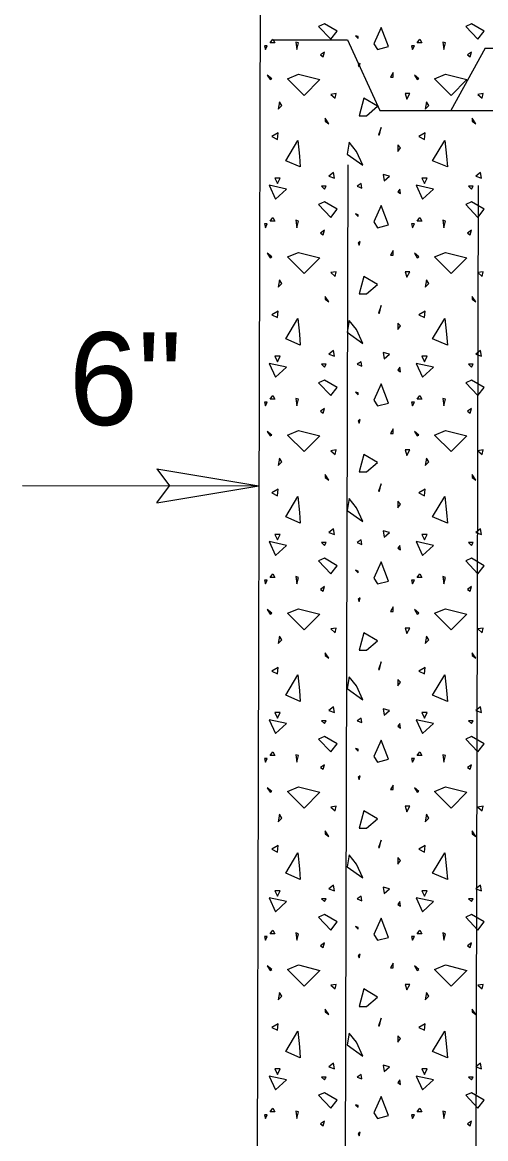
# Model space of a CAD drawing. Extents: x 9.6 to 16.8, y 2.2 to 12.2.
# Drawn here: x 14.697 to 14.996, y 7.48 to 8.202 of the extents above; entities that cross this region are included whole.
import ezdxf

# ---------------------------------------------------------------- set-up
doc = ezdxf.new("R2010")
doc.units = 0
for name, color, linetype in [('DETL-DIMS', 7, 'Continuous'), ('DETL-LINE', 7, 'Continuous'), ('DETL-NOTE', 7, 'Continuous'), ('DETL-PATT', 7, 'Continuous')]:
    doc.layers.add(name, color=color, linetype=linetype)

msp = doc.modelspace()

# ---------------------------------------------------------------- linework, layer by layer
at = {"layer": 'DETL-DIMS'}
for p, q in [((14.78357, 7.91357), (14.84941, 7.90247)), ((14.78357, 7.91357), (14.79176, 7.90259)), ((14.69659, 7.90278), (14.84941, 7.90247)), ((14.78349, 7.89161), (14.79176, 7.90259)), ((14.78349, 7.89161), (14.84941, 7.90247))]:
    msp.add_line(p, q, dxfattribs=at)
at = {"layer": 'DETL-LINE'}
for p, q in [((14.85165, 8.75561), (14.84702, 6.99)), ((14.85804, 8.19102), (14.90675, 8.1909)), ((14.90675, 8.1909), (14.92769, 8.14525)), ((14.99573, 8.18549), (14.97361, 8.14518)), ((14.99573, 8.18549), (16.02733, 8.18278)), ((14.92769, 8.14525), (14.97361, 8.14518)), ((14.97361, 8.14518), (16.04459, 8.14518)), ((14.90698, 8.11008), (14.90412, 7.02231)), ((14.99129, 8.09671), (14.98867, 7.08824))]:
    msp.add_line(p, q, dxfattribs=at)
at = {"layer": 'DETL-PATT'}
for points in [[(14.88812, 8.19961), (14.89588, 8.19129), (14.90012, 8.19651), (14.8918, 8.20133)], [(14.98314, 8.19961), (14.9909, 8.19129), (14.99514, 8.19651), (14.98682, 8.20133)], [(14.91369, 8.19298), (14.912, 8.19357), (14.91369, 8.19184)], [(14.92624, 8.18467), (14.93329, 8.18651), (14.92851, 8.1989), (14.92384, 8.18831)], [(14.8531, 8.18706), (14.85369, 8.18467), (14.85494, 8.18706)], [(14.85847, 8.19129), (14.85976, 8.1889), (14.85678, 8.1889)], [(14.87329, 8.18945), (14.874, 8.18467), (14.87514, 8.1889)], [(14.94812, 8.18706), (14.94871, 8.18467), (14.94996, 8.18706)], [(14.95349, 8.19129), (14.95475, 8.1889), (14.9518, 8.1889)], [(14.96831, 8.18945), (14.96902, 8.18467), (14.97016, 8.1889)], [(14.88941, 8.18114), (14.8911, 8.18), (14.8918, 8.18298)], [(14.98439, 8.18114), (14.98612, 8.18), (14.98682, 8.18298)], [(14.91494, 8.17576), (14.91369, 8.17463), (14.91439, 8.17337)], [(14.85678, 8.16518), (14.85792, 8.16573), (14.85494, 8.16816)], [(14.87514, 8.16871), (14.88882, 8.16518), (14.87867, 8.15502), (14.86792, 8.16573)], [(14.93627, 8.16984), (14.93459, 8.16686), (14.93627, 8.16686)], [(14.9518, 8.16518), (14.95294, 8.16573), (14.94996, 8.16816)], [(14.97016, 8.16871), (14.98384, 8.16518), (14.97369, 8.15502), (14.96294, 8.16573)], [(14.86271, 8.1509), (14.862, 8.14612), (14.86439, 8.14851)], [(14.89588, 8.15557), (14.89886, 8.15318), (14.89941, 8.15616)], [(14.91906, 8.14188), (14.92624, 8.14796), (14.91733, 8.15318), (14.91439, 8.14188)], [(14.94404, 8.15616), (14.94518, 8.15263), (14.94698, 8.15616)], [(14.95773, 8.1509), (14.95702, 8.14612), (14.95941, 8.14851)], [(14.9909, 8.15557), (14.99388, 8.15318), (14.99443, 8.15616)], [(14.89235, 8.1402), (14.89235, 8.13835), (14.89475, 8.13667)], [(14.98737, 8.1402), (14.98737, 8.13835), (14.98976, 8.13667)], [(14.85792, 8.12831), (14.86145, 8.12651), (14.862, 8.13075)], [(14.92682, 8.12945), (14.92737, 8.12945), (14.92851, 8.13427)], [(14.95294, 8.12831), (14.95647, 8.12651), (14.95702, 8.13075)], [(14.87569, 8.11576), (14.87627, 8.10871), (14.86682, 8.11278), (14.87459, 8.12592)], [(14.90776, 8.12467), (14.90663, 8.11702), (14.91663, 8.10984), (14.91255, 8.11875)], [(14.93922, 8.12298), (14.93922, 8.11875), (14.94106, 8.12114)], [(14.97071, 8.11576), (14.97129, 8.10871), (14.9618, 8.11278), (14.96957, 8.12592)], [(14.85976, 8.10149), (14.86145, 8.09796), (14.86329, 8.10149)], [(14.89773, 8.10518), (14.89475, 8.10278), (14.89827, 8.10149)], [(14.92976, 8.10392), (14.93035, 8.0998), (14.93388, 8.10278)], [(14.95475, 8.10149), (14.95647, 8.09796), (14.95827, 8.10149)], [(14.99275, 8.10518), (14.98976, 8.10278), (14.99329, 8.10149)], [(14.85608, 8.09686), (14.86031, 8.08796), (14.86737, 8.09443)], [(14.88996, 8.09627), (14.8918, 8.09443), (14.89294, 8.09627)], [(14.9131, 8.09627), (14.91608, 8.09502), (14.91553, 8.09796)], [(14.93922, 8.09263), (14.94106, 8.09149), (14.94051, 8.09443)], [(14.9511, 8.09686), (14.95533, 8.08796), (14.96239, 8.09443)], [(14.98498, 8.09627), (14.98682, 8.09443), (14.98792, 8.09627)], [(14.88812, 8.08443), (14.89588, 8.07608), (14.90012, 8.08133), (14.8918, 8.08612)], [(14.98314, 8.08443), (14.9909, 8.07608), (14.99514, 8.08133), (14.98682, 8.08612)], [(14.91369, 8.0778), (14.912, 8.07835), (14.91369, 8.07667)], [(14.92624, 8.06945), (14.93329, 8.07129), (14.92851, 8.08373), (14.92384, 8.07314)], [(14.8531, 8.07184), (14.85369, 8.06945), (14.85494, 8.07184)], [(14.85847, 8.07608), (14.85976, 8.07369), (14.85678, 8.07369)], [(14.87329, 8.07427), (14.874, 8.06945), (14.87514, 8.07369)], [(14.94812, 8.07184), (14.94871, 8.06945), (14.94996, 8.07184)], [(14.95349, 8.07608), (14.95475, 8.07369), (14.9518, 8.07369)], [(14.96831, 8.07427), (14.96902, 8.06945), (14.97016, 8.07369)], [(14.88941, 8.06592), (14.8911, 8.06478), (14.8918, 8.06776)], [(14.98439, 8.06592), (14.98612, 8.06478), (14.98682, 8.06776)], [(14.91494, 8.06055), (14.91369, 8.05945), (14.91439, 8.05816)], [(14.85678, 8.04996), (14.85792, 8.05055), (14.85494, 8.05294)], [(14.87514, 8.05349), (14.88882, 8.04996), (14.87867, 8.0398), (14.86792, 8.05055)], [(14.93627, 8.05463), (14.93459, 8.05169), (14.93627, 8.05169)], [(14.9518, 8.04996), (14.95294, 8.05055), (14.94996, 8.05294)], [(14.97016, 8.05349), (14.98384, 8.04996), (14.97369, 8.0398), (14.96294, 8.05055)], [(14.86271, 8.03573), (14.862, 8.0309), (14.86439, 8.03333)], [(14.89588, 8.04039), (14.89886, 8.03796), (14.89941, 8.04094)], [(14.91906, 8.02667), (14.92624, 8.03275), (14.91733, 8.03796), (14.91439, 8.02667)], [(14.94404, 8.04094), (14.94518, 8.03741), (14.94698, 8.04094)], [(14.95773, 8.03573), (14.95702, 8.0309), (14.95941, 8.03333)], [(14.9909, 8.04039), (14.99388, 8.03796), (14.99443, 8.04094)], [(14.89235, 8.02498), (14.89235, 8.02314), (14.89475, 8.02145)], [(14.98737, 8.02498), (14.98737, 8.02314), (14.98976, 8.02145)], [(14.85792, 8.01314), (14.86145, 8.01129), (14.862, 8.01553)], [(14.92682, 8.01427), (14.92737, 8.01427), (14.92851, 8.01906)], [(14.95294, 8.01314), (14.95647, 8.01129), (14.95702, 8.01553)], [(14.87569, 8.00055), (14.87627, 7.99349), (14.86682, 7.99761), (14.87459, 8.01075)], [(14.90776, 8.00945), (14.90663, 8.00184), (14.91663, 7.99463), (14.91255, 8.00353)], [(14.93922, 8.00776), (14.93922, 8.00353), (14.94106, 8.00592)], [(14.97071, 8.00055), (14.97129, 7.99349), (14.9618, 7.99761), (14.96957, 8.01075)], [(14.85976, 7.98631), (14.86145, 7.98278), (14.86329, 7.98631)], [(14.89773, 7.98996), (14.89475, 7.98757), (14.89827, 7.98631)], [(14.92976, 7.98871), (14.93035, 7.98463), (14.93388, 7.98757)], [(14.95475, 7.98631), (14.95647, 7.98278), (14.95827, 7.98631)], [(14.99275, 7.98996), (14.98976, 7.98757), (14.99329, 7.98631)], [(14.85608, 7.98165), (14.86031, 7.97275), (14.86737, 7.97925)], [(14.88996, 7.9811), (14.8918, 7.97925), (14.89294, 7.9811)], [(14.9131, 7.9811), (14.91608, 7.9798), (14.91553, 7.98278)], [(14.93922, 7.97741), (14.94106, 7.97627), (14.94051, 7.97925)], [(14.9511, 7.98165), (14.95533, 7.97275), (14.96239, 7.97925)], [(14.98498, 7.9811), (14.98682, 7.97925), (14.98792, 7.9811)], [(14.88812, 7.96922), (14.89588, 7.9609), (14.90012, 7.96612), (14.8918, 7.9709)], [(14.98314, 7.96922), (14.9909, 7.9609), (14.99514, 7.96612), (14.98682, 7.9709)], [(14.91369, 7.96259), (14.912, 7.96314), (14.91369, 7.96145)], [(14.92624, 7.95427), (14.93329, 7.95608), (14.92851, 7.96851), (14.92384, 7.95792)], [(14.8531, 7.95667), (14.85369, 7.95427), (14.85494, 7.95667)], [(14.85847, 7.9609), (14.85976, 7.95851), (14.85678, 7.95851)], [(14.87329, 7.95906), (14.874, 7.95427), (14.87514, 7.95851)], [(14.94812, 7.95667), (14.94871, 7.95427), (14.94996, 7.95667)], [(14.95349, 7.9609), (14.95475, 7.95851), (14.9518, 7.95851)], [(14.96831, 7.95906), (14.96902, 7.95427), (14.97016, 7.95851)], [(14.88941, 7.95075), (14.8911, 7.94961), (14.8918, 7.95255)], [(14.98439, 7.95075), (14.98612, 7.94961), (14.98682, 7.95255)], [(14.91494, 7.94537), (14.91369, 7.94424), (14.91439, 7.94298)], [(14.85678, 7.93478), (14.85792, 7.93533), (14.85494, 7.93773)], [(14.87514, 7.93831), (14.88882, 7.93478), (14.87867, 7.92463), (14.86792, 7.93533)], [(14.93627, 7.93945), (14.93459, 7.93647), (14.93627, 7.93647)], [(14.9518, 7.93478), (14.95294, 7.93533), (14.94996, 7.93773)], [(14.97016, 7.93831), (14.98384, 7.93478), (14.97369, 7.92463), (14.96294, 7.93533)], [(14.86271, 7.92051), (14.862, 7.91573), (14.86439, 7.91812)], [(14.89588, 7.92518), (14.89886, 7.92278), (14.89941, 7.92573)], [(14.91906, 7.91149), (14.92624, 7.91757), (14.91733, 7.92278), (14.91439, 7.91149)], [(14.94404, 7.92573), (14.94518, 7.9222), (14.94698, 7.92573)], [(14.95773, 7.92051), (14.95702, 7.91573), (14.95941, 7.91812)], [(14.9909, 7.92518), (14.99388, 7.92278), (14.99443, 7.92573)], [(14.89235, 7.9098), (14.89235, 7.90796), (14.89475, 7.90627)], [(14.98737, 7.9098), (14.98737, 7.90796), (14.98976, 7.90627)], [(14.85792, 7.89792), (14.86145, 7.89608), (14.862, 7.90031)], [(14.92682, 7.89906), (14.92737, 7.89906), (14.92851, 7.90384)], [(14.95294, 7.89792), (14.95647, 7.89608), (14.95702, 7.90031)], [(14.87569, 7.88537), (14.87627, 7.87831), (14.86682, 7.88239), (14.87459, 7.89553)], [(14.90776, 7.89427), (14.90663, 7.88663), (14.91663, 7.87945), (14.91255, 7.88831)], [(14.93922, 7.89255), (14.93922, 7.88831), (14.94106, 7.89075)], [(14.97071, 7.88537), (14.97129, 7.87831), (14.9618, 7.88239), (14.96957, 7.89553)], [(14.85976, 7.8711), (14.86145, 7.86757), (14.86329, 7.8711)], [(14.89773, 7.87478), (14.89475, 7.87239), (14.89827, 7.8711)], [(14.92976, 7.87349), (14.93035, 7.86941), (14.93388, 7.87239)], [(14.95475, 7.8711), (14.95647, 7.86757), (14.95827, 7.8711)], [(14.99275, 7.87478), (14.98976, 7.87239), (14.99329, 7.8711)], [(14.85608, 7.86643), (14.86031, 7.85757), (14.86737, 7.86404)], [(14.88996, 7.86588), (14.8918, 7.86404), (14.89294, 7.86588)], [(14.9131, 7.86588), (14.91608, 7.86463), (14.91553, 7.86757)], [(14.93922, 7.8622), (14.94106, 7.8611), (14.94051, 7.86404)], [(14.9511, 7.86643), (14.95533, 7.85757), (14.96239, 7.86404)], [(14.98498, 7.86588), (14.98682, 7.86404), (14.98792, 7.86588)], [(14.88812, 7.85404), (14.89588, 7.84569), (14.90012, 7.8509), (14.8918, 7.85573)], [(14.98314, 7.85404), (14.9909, 7.84569), (14.99514, 7.8509), (14.98682, 7.85573)], [(14.91369, 7.84737), (14.912, 7.84796), (14.91369, 7.84627)], [(14.92624, 7.83906), (14.93329, 7.8409), (14.92851, 7.85333), (14.92384, 7.84275)], [(14.8531, 7.84145), (14.85369, 7.83906), (14.85494, 7.84145)], [(14.85847, 7.84569), (14.85976, 7.84329), (14.85678, 7.84329)], [(14.87329, 7.84384), (14.874, 7.83906), (14.87514, 7.84329)], [(14.94812, 7.84145), (14.94871, 7.83906), (14.94996, 7.84145)], [(14.95349, 7.84569), (14.95475, 7.84329), (14.9518, 7.84329)], [(14.96831, 7.84384), (14.96902, 7.83906), (14.97016, 7.84329)], [(14.88941, 7.83553), (14.8911, 7.83439), (14.8918, 7.83737)], [(14.98439, 7.83553), (14.98612, 7.83439), (14.98682, 7.83737)], [(14.91494, 7.83016), (14.91369, 7.82902), (14.91439, 7.82776)], [(14.85678, 7.81957), (14.85792, 7.82016), (14.85494, 7.82255)], [(14.87514, 7.8231), (14.88882, 7.81957), (14.87867, 7.80941), (14.86792, 7.82016)], [(14.93627, 7.82424), (14.93459, 7.82125), (14.93627, 7.82125)], [(14.9518, 7.81957), (14.95294, 7.82016), (14.94996, 7.82255)], [(14.97016, 7.8231), (14.98384, 7.81957), (14.97369, 7.80941), (14.96294, 7.82016)], [(14.89588, 7.80996), (14.89886, 7.80757), (14.89941, 7.81055)], [(14.94404, 7.81055), (14.94518, 7.80702), (14.94698, 7.81055)], [(14.9909, 7.80996), (14.99388, 7.80757), (14.99443, 7.81055)], [(14.86271, 7.80533), (14.862, 7.80051), (14.86439, 7.8029)], [(14.91906, 7.79627), (14.92624, 7.80235), (14.91733, 7.80757), (14.91439, 7.79627)], [(14.95773, 7.80533), (14.95702, 7.80051), (14.95941, 7.8029)], [(14.89235, 7.79459), (14.89235, 7.79275), (14.89475, 7.79106)], [(14.98737, 7.79459), (14.98737, 7.79275), (14.98976, 7.79106)], [(14.85792, 7.78275), (14.86145, 7.7809), (14.862, 7.78514)], [(14.92682, 7.78384), (14.92737, 7.78384), (14.92851, 7.78867)], [(14.95294, 7.78275), (14.95647, 7.7809), (14.95702, 7.78514)], [(14.87569, 7.77016), (14.87627, 7.7631), (14.86682, 7.76722), (14.87459, 7.78031)], [(14.90776, 7.77906), (14.90663, 7.77145), (14.91663, 7.76424), (14.91255, 7.77314)], [(14.93922, 7.77737), (14.93922, 7.77314), (14.94106, 7.77553)], [(14.97071, 7.77016), (14.97129, 7.7631), (14.9618, 7.76722), (14.96957, 7.78031)], [(14.85976, 7.75592), (14.86145, 7.75239), (14.86329, 7.75592)], [(14.89773, 7.75957), (14.89475, 7.75718), (14.89827, 7.75592)], [(14.92976, 7.75831), (14.93035, 7.7542), (14.93388, 7.75718)], [(14.95475, 7.75592), (14.95647, 7.75239), (14.95827, 7.75592)], [(14.99275, 7.75957), (14.98976, 7.75718), (14.99329, 7.75592)], [(14.85608, 7.75125), (14.86031, 7.74235), (14.86737, 7.74886)], [(14.88996, 7.75067), (14.8918, 7.74886), (14.89294, 7.75067)], [(14.9131, 7.75067), (14.91608, 7.74941), (14.91553, 7.75239)], [(14.93922, 7.74702), (14.94106, 7.74588), (14.94051, 7.74886)], [(14.9511, 7.75125), (14.95533, 7.74235), (14.96239, 7.74886)], [(14.98498, 7.75067), (14.98682, 7.74886), (14.98792, 7.75067)], [(14.88812, 7.73882), (14.89588, 7.73051), (14.90012, 7.73573), (14.8918, 7.74051)], [(14.98314, 7.73882), (14.9909, 7.73051), (14.99514, 7.73573), (14.98682, 7.74051)], [(14.91369, 7.7322), (14.912, 7.73275), (14.91369, 7.73106)], [(14.92624, 7.72384), (14.93329, 7.72569), (14.92851, 7.73812), (14.92384, 7.72753)], [(14.8531, 7.72627), (14.85369, 7.72384), (14.85494, 7.72627)], [(14.85847, 7.73051), (14.85976, 7.72808), (14.85678, 7.72808)], [(14.87329, 7.72867), (14.874, 7.72384), (14.87514, 7.72808)], [(14.94812, 7.72627), (14.94871, 7.72384), (14.94996, 7.72627)], [(14.95349, 7.73051), (14.95475, 7.72808), (14.9518, 7.72808)], [(14.96831, 7.72867), (14.96902, 7.72384), (14.97016, 7.72808)], [(14.88941, 7.72031), (14.8911, 7.71922), (14.8918, 7.72216)], [(14.98439, 7.72031), (14.98612, 7.71922), (14.98682, 7.72216)], [(14.91494, 7.71498), (14.91369, 7.71384), (14.91439, 7.71255)], [(14.85678, 7.70439), (14.85792, 7.70494), (14.85494, 7.70733)], [(14.87514, 7.70792), (14.88882, 7.70439), (14.87867, 7.6942), (14.86792, 7.70494)], [(14.93627, 7.70902), (14.93459, 7.70608), (14.93627, 7.70608)], [(14.9518, 7.70439), (14.95294, 7.70494), (14.94996, 7.70733)], [(14.97016, 7.70792), (14.98384, 7.70439), (14.97369, 7.6942), (14.96294, 7.70494)], [(14.89588, 7.69478), (14.89886, 7.69239), (14.89941, 7.69533)], [(14.94404, 7.69533), (14.94518, 7.6918), (14.94698, 7.69533)], [(14.9909, 7.69478), (14.99388, 7.69239), (14.99443, 7.69533)], [(14.86271, 7.69012), (14.862, 7.68533), (14.86439, 7.68773)], [(14.91906, 7.6811), (14.92624, 7.68714), (14.91733, 7.69239), (14.91439, 7.6811)], [(14.95773, 7.69012), (14.95702, 7.68533), (14.95941, 7.68773)], [(14.89235, 7.67937), (14.89235, 7.67757), (14.89475, 7.67584)], [(14.92682, 7.66867), (14.92737, 7.66867), (14.92851, 7.67345)], [(14.98737, 7.67937), (14.98737, 7.67757), (14.98976, 7.67584)], [(14.85792, 7.66753), (14.86145, 7.66569), (14.862, 7.66992)], [(14.95294, 7.66753), (14.95647, 7.66569), (14.95702, 7.66992)], [(14.87569, 7.65498), (14.87627, 7.64792), (14.86682, 7.652), (14.87459, 7.66514)], [(14.90776, 7.66384), (14.90663, 7.65624), (14.91663, 7.64902), (14.91255, 7.65792)], [(14.93922, 7.66216), (14.93922, 7.65792), (14.94106, 7.66031)], [(14.97071, 7.65498), (14.97129, 7.64792), (14.9618, 7.652), (14.96957, 7.66514)], [(14.89773, 7.64439), (14.89475, 7.64196), (14.89827, 7.64071)], [(14.99275, 7.64439), (14.98976, 7.64196), (14.99329, 7.64071)], [(14.85976, 7.64071), (14.86145, 7.63718), (14.86329, 7.64071)], [(14.9131, 7.63549), (14.91608, 7.6342), (14.91553, 7.63718)], [(14.92976, 7.6431), (14.93035, 7.63902), (14.93388, 7.64196)], [(14.95475, 7.64071), (14.95647, 7.63718), (14.95827, 7.64071)], [(14.85608, 7.63604), (14.86031, 7.62714), (14.86737, 7.63365)], [(14.88996, 7.63549), (14.8918, 7.63365), (14.89294, 7.63549)], [(14.93922, 7.6318), (14.94106, 7.63067), (14.94051, 7.63365)], [(14.9511, 7.63604), (14.95533, 7.62714), (14.96239, 7.63365)], [(14.98498, 7.63549), (14.98682, 7.63365), (14.98792, 7.63549)], [(14.88812, 7.62361), (14.89588, 7.61529), (14.90012, 7.62051), (14.8918, 7.62533)], [(14.92624, 7.60867), (14.93329, 7.61051), (14.92851, 7.6229), (14.92384, 7.61231)], [(14.98314, 7.62361), (14.9909, 7.61529), (14.99514, 7.62051), (14.98682, 7.62533)], [(14.91369, 7.61698), (14.912, 7.61757), (14.91369, 7.61584)], [(14.8531, 7.61106), (14.85369, 7.60867), (14.85494, 7.61106)], [(14.85847, 7.61529), (14.85976, 7.6129), (14.85678, 7.6129)], [(14.87329, 7.61345), (14.874, 7.60867), (14.87514, 7.6129)], [(14.94812, 7.61106), (14.94871, 7.60867), (14.94996, 7.61106)], [(14.95349, 7.61529), (14.95475, 7.6129), (14.9518, 7.6129)], [(14.96831, 7.61345), (14.96902, 7.60867), (14.97016, 7.6129)], [(14.88941, 7.60514), (14.8911, 7.604), (14.8918, 7.60698)], [(14.98439, 7.60514), (14.98612, 7.604), (14.98682, 7.60698)], [(14.91494, 7.59976), (14.91369, 7.59863), (14.91439, 7.59737)], [(14.93627, 7.59384), (14.93459, 7.59086), (14.93627, 7.59086)], [(14.85678, 7.58918), (14.85792, 7.58973), (14.85494, 7.59216)], [(14.87514, 7.59271), (14.88882, 7.58918), (14.87867, 7.57902), (14.86792, 7.58973)], [(14.9518, 7.58918), (14.95294, 7.58973), (14.94996, 7.59216)], [(14.97016, 7.59271), (14.98384, 7.58918), (14.97369, 7.57902), (14.96294, 7.58973)], [(14.89588, 7.57957), (14.89886, 7.57718), (14.89941, 7.58016)], [(14.94404, 7.58016), (14.94518, 7.57663), (14.94698, 7.58016)], [(14.9909, 7.57957), (14.99388, 7.57718), (14.99443, 7.58016)], [(14.86271, 7.5749), (14.862, 7.57012), (14.86439, 7.57251)], [(14.91906, 7.56588), (14.92624, 7.57196), (14.91733, 7.57718), (14.91439, 7.56588)], [(14.95773, 7.5749), (14.95702, 7.57012), (14.95941, 7.57251)], [(14.89235, 7.5642), (14.89235, 7.56235), (14.89475, 7.56067)], [(14.92682, 7.55345), (14.92737, 7.55345), (14.92851, 7.55827)], [(14.98737, 7.5642), (14.98737, 7.56235), (14.98976, 7.56067)], [(14.85792, 7.55231), (14.86145, 7.55051), (14.862, 7.55475)], [(14.95294, 7.55231), (14.95647, 7.55051), (14.95702, 7.55475)], [(14.87569, 7.53976), (14.87627, 7.53271), (14.86682, 7.53678), (14.87459, 7.54992)], [(14.90776, 7.54867), (14.90663, 7.54102), (14.91663, 7.53384), (14.91255, 7.54275)], [(14.93922, 7.54698), (14.93922, 7.54275), (14.94106, 7.54514)], [(14.97071, 7.53976), (14.97129, 7.53271), (14.9618, 7.53678), (14.96957, 7.54992)], [(14.89773, 7.52918), (14.89475, 7.52678), (14.89827, 7.52549)], [(14.99275, 7.52918), (14.98976, 7.52678), (14.99329, 7.52549)], [(14.85976, 7.52549), (14.86145, 7.52196), (14.86329, 7.52549)], [(14.9131, 7.52027), (14.91608, 7.51902), (14.91553, 7.52196)], [(14.92976, 7.52792), (14.93035, 7.5238), (14.93388, 7.52678)], [(14.95475, 7.52549), (14.95647, 7.52196), (14.95827, 7.52549)], [(14.85608, 7.52086), (14.86031, 7.51196), (14.86737, 7.51843)], [(14.88996, 7.52027), (14.8918, 7.51843), (14.89294, 7.52027)], [(14.93922, 7.51663), (14.94106, 7.51549), (14.94051, 7.51843)], [(14.9511, 7.52086), (14.95533, 7.51196), (14.96239, 7.51843)], [(14.98498, 7.52027), (14.98682, 7.51843), (14.98792, 7.52027)], [(14.88812, 7.50843), (14.89588, 7.50008), (14.90012, 7.50533), (14.8918, 7.51012)], [(14.92624, 7.49345), (14.93329, 7.49529), (14.92851, 7.50773), (14.92384, 7.49714)], [(14.98314, 7.50843), (14.9909, 7.50008), (14.99514, 7.50533), (14.98682, 7.51012)], [(14.85847, 7.50008), (14.85976, 7.49769), (14.85678, 7.49769)], [(14.91369, 7.5018), (14.912, 7.50235), (14.91369, 7.50067)], [(14.95349, 7.50008), (14.95475, 7.49769), (14.9518, 7.49769)], [(14.8531, 7.49584), (14.85369, 7.49345), (14.85494, 7.49584)], [(14.87329, 7.49827), (14.874, 7.49345), (14.87514, 7.49769)], [(14.94812, 7.49584), (14.94871, 7.49345), (14.94996, 7.49584)], [(14.96831, 7.49827), (14.96902, 7.49345), (14.97016, 7.49769)], [(14.88941, 7.48992), (14.8911, 7.48878), (14.8918, 7.49176)], [(14.98439, 7.48992), (14.98612, 7.48878), (14.98682, 7.49176)], [(14.91494, 7.48455), (14.91369, 7.48345), (14.91439, 7.48216)]]:
    msp.add_lwpolyline(points, close=True, dxfattribs=at)

# ---------------------------------------------------------------- texts
at = {"layer": 'DETL-NOTE'}
msp.add_text('6"', height=0.06, dxfattribs=at).set_placement((14.72667, 7.94184))

doc.saveas('drawing.dxf')
